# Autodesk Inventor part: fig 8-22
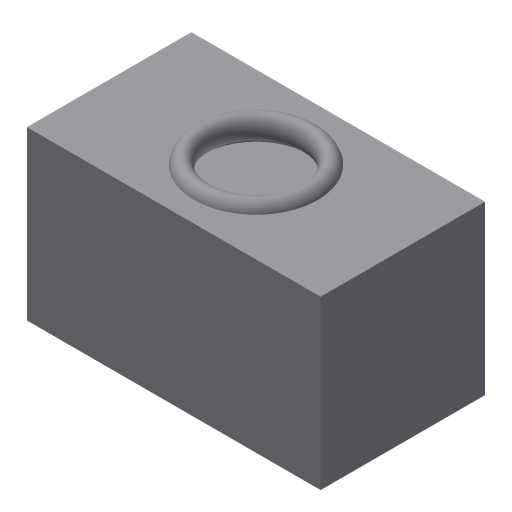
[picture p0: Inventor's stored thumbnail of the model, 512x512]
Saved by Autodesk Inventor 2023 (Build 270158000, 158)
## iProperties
Created: 2011-07
Part Number: fig 8-22
Material: Generic
Document SubType Name: Modeling
Designer: CadCim
Density: 1 g/cm^3
Appearance: Default
Author: CadCim
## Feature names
1. Extrusion1
2. Extrusion2
3. Sweep1
## Parameters: d0 = 14.25 mm, d1 = 0, d2 = 1.5 mm, d3 = 0, d4 = -4.25 mm, d5 = 0, d6 = 0
